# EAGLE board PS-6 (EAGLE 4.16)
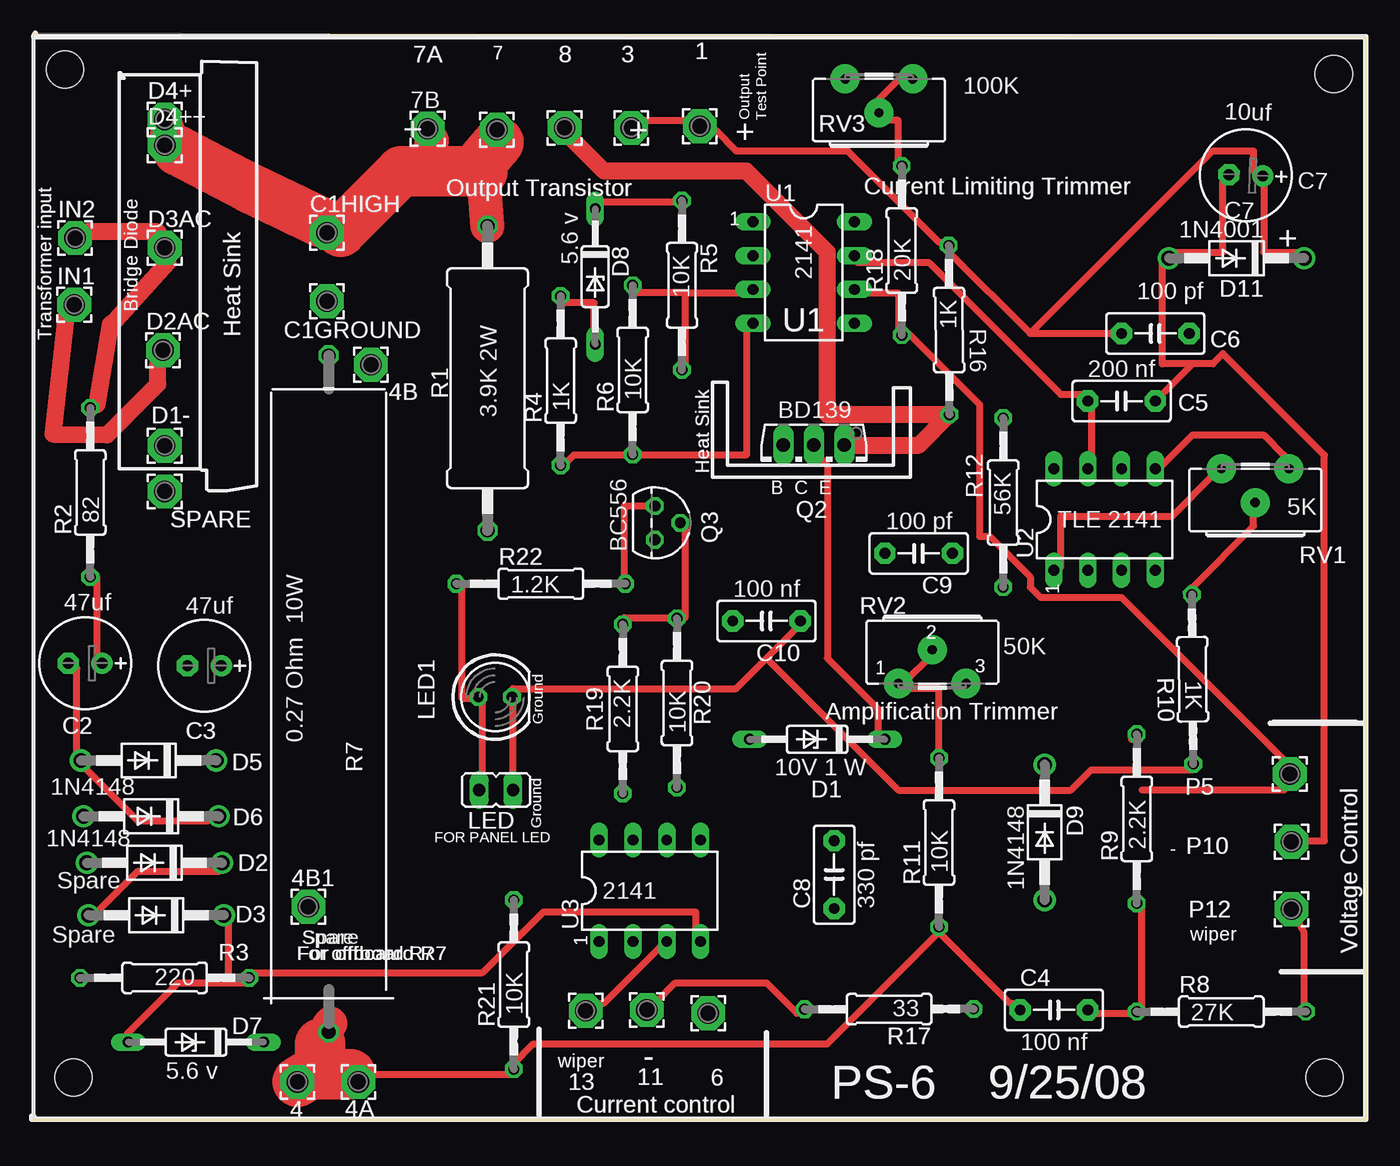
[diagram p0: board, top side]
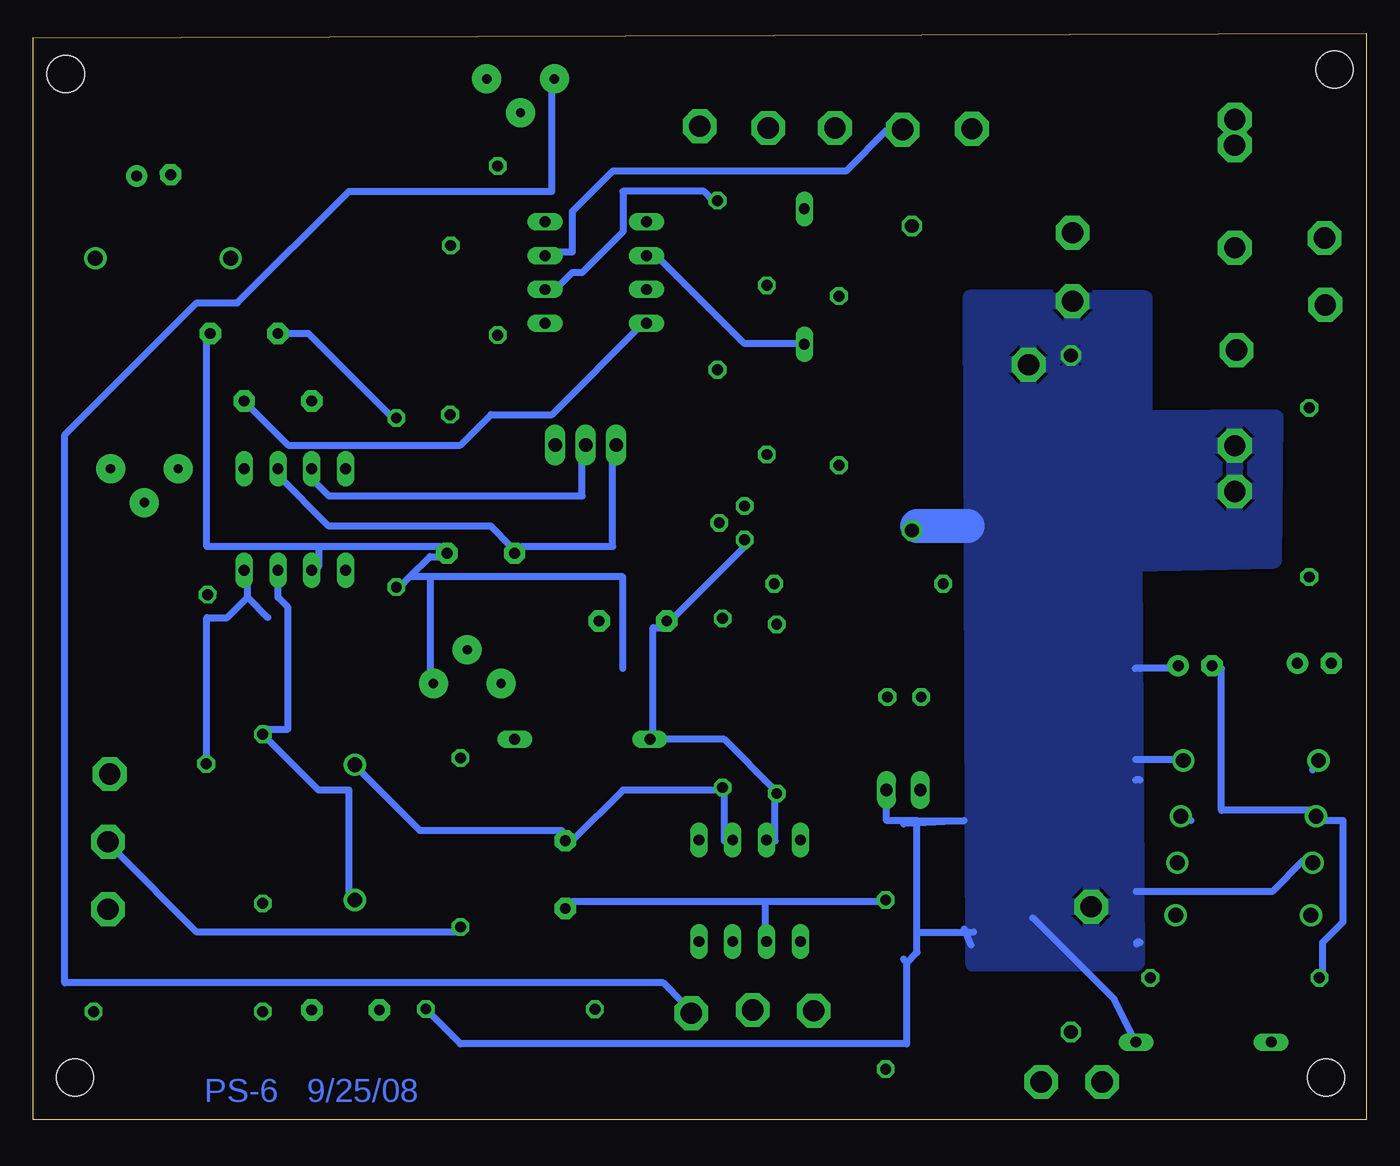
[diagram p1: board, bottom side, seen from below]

Size 100.13 x 81.59 mm. Coordinates in mm from the lower left corner, seen from the top.
Outline: 0,0 100.13,0 100.13,81.27 0,81.59 0,0
Copper layers (1*16): Top 0.035mm / dielectric 1.5mm / Bottom 0.035mm
Design rules "default": minimum track width 15mil, minimum drill 6mil, track to track 10mil, track to pad 8mil, pad to pad 8mil, via to via 8mil, smd to smd 8mil, copper to edge 20mil, drill to drill 6mil, minimum pad ring 10mil, minimum via ring 15mil, stop-mask expansion 4mil, vias tented up to drill 0mil, thermal gap 10mil
Net classes: 0 default: width 0.508 mm, drill 0.635 mm; 1 POWER: width 0.508 mm, drill 0.635 mm; 2 HI power: width 0.508 mm, drill 0.508 mm; 3 VPower: width 0.508 mm, drill 0.508 mm
Holes 2.8 mm at 97.69,78.54 96.99,3.17 3.01,3.17 2.38,78.86

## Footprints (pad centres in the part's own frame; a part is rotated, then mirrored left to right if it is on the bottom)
2,54/0,8 = drill 1.6 pad 2.54 octagon: 1 0,0
E2,5-7 = drill 0.813 pad 1.6 round: + -1.27,0 | drill 0.813 pad 1.6 octagon: - 1.27,0
C5B3 = drill 0.813 pad 1.6 octagon: 1 -2.54,0; 2 2.54,0
DO35Z10 = drill 0.813 long: A 5.08,0; C -5.08,0
DO41-10 = drill 1.118 round: A 5.08,0; C -5.08,0
JP1 = drill 0.914 long: 1 0,-1.27; 2 0,1.27
LED5MM = drill 0.813 octagon: A -1.27,0; K 1.27,0
TO126AV = drill 1.016 long: B 2.286,-1.27; C 0,-1.27; E -2.286,-1.27
TO92 = drill 0.813 octagon: 1 1.27,0; 2 0,1.905; 3 -1.27,0
0617/22 = drill 1.016 octagon: 1 -11.43,0; 2 11.43,0
0207/12 = drill 0.813 octagon: 1 -6.35,0; 2 6.35,0
POWERRESISTOR = drill 1.016 octagon: 1 -12.7,0; 2 38.1,0
POTT = drill 0.7 pad 2.184 round: P$1 -2.54,0; P$2 2.54,0; P$3 0,2.54
DIL08 = drill 0.813 long: 1 -3.81,-3.81; 2 -1.27,-3.81; 3 1.27,-3.81; 4 3.81,-3.81; 5 3.81,3.81; 6 1.27,3.81; 7 -1.27,3.81; 8 -3.81,3.81

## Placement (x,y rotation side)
1  [2,54/0,8]  50.06,74.61 0 top
3  [2,54/0,8]  44.92,74.48 90 top
4  [2,54/0,8]  19.85,2.84 0 top
4A  [2,54/0,8]  24.42,2.84 0 top
4B  [2,54/0,8]  25.36,56.7 0 top
4B1  [2,54/0,8]  20.66,16 0 top
6  [2,54/0,8]  50.7,8 0 top
7A  [2,54/0,8]  34.82,74.35 0 top
7B  7  [2,54/0,8]  29.62,74.42 0 top
8  [2,54/0,8]  39.9,74.48 0 top
11  11  [2,54/0,8]  46.09,8.25 0 top
13  [2,54/0,8]  41.5,8.19 0 top
C1GROUND  [2,54/0,8]  22.06,61.46 0 top
C1HIGH  [2,54/0,8]  22.06,66.61 0 top
C2  47uf  [E2,5-7]  3.9,34.28 180 top
C3  47uf  [E2,5-7]  12.85,34.09 180 top
C4  100 nf  [C5B3]  76.67,8.25 0 top
C5  200 nf  [C5B3]  81.75,53.97 180 top
C6  100 pf  [C5B3]  84.29,59.05 180 top
C7  10uf  [E2,5-7]  91.08,70.92 177.9 top
C8  330 pf  [C5B3]  60.16,18.41 90 top
C9  100 pf  [C5B3]  66.51,42.54 180 top
C10  100 nf  [C5B3]  55.08,37.46 180 top
D1  10V 1 W  [DO35Z10]  58.89,28.57 180 top
D1-  [2,54/0,8]  9.87,50.62 0 top
D2  Spare  [DO41-10]  9.11,19.3 180 top
D2AC  [2,54/0,8]  9.74,57.8 0 top
D3  Spare  [DO41-10]  9.23,15.36 180 top
D3AC  [2,54/0,8]  9.87,65.48 0 top
D4+  [2,54/0,8]  9.87,75.12 0 top
D4++  [2,54/0,8]  9.88,73.18 0 top
D5  1N4148  [DO41-10]  8.66,26.98 180 top
D6  1N4148  [DO41-10]  8.85,22.79 180 top
D7  5.6 v  [DO35Z10]  12.22,5.84 180 top
D8  5.6 v  [DO35Z10]  42.21,63.32 270 top
D9  1N4148  [DO41-10]  75.97,21.58 270 top
D11  1N4001  [DO41-10]  90.39,64.7 180 top
IN1  [2,54/0,8]  3.07,61.19 0 top
IN2  [2,54/0,8]  3.14,66.21 0 top
LED  [JP1]  34.76,24.76 90 top
LED1  [LED5MM]  34.7,31.74 0 top
P5  [2,54/0,8]  94.39,25.97 0 top
P10  [2,54/0,8]  94.51,20.89 0 top
P12  [2,54/0,8]  94.51,15.81 0 top
Q2  BD139  [TO126AV]  58.64,49.4 180 top
Q3  BC556  [TO92]  46.7,44.83 270 top
R1  3.9K 2W  [0617/22]  34.12,55.68 90 top
R2  82  [0207/12]  4.28,47.11 90 top
R3  220  [0207/12]  9.87,10.66 180 top
R4  1K  [0207/12]  39.61,55.5 90 top
R5  10K  [0207/12]  48.73,62.67 270 top
R6  10K  [0207/12]  45.02,56.31 90 top
R7  0.27 Ohm 10W  [POWERRESISTOR]  22.19,44.7 270 top
R8  27K  [0207/12]  89.24,8.12 0 top
R9  2.2K  [0207/12]  82.89,22.6 90 top
R10  1K  [0207/12]  87.08,33.08 90.5 top
R11  10K  [0207/12]  68.03,20.82 90 top
R12  56K  [0207/12]  72.86,46.35 270 top
R16  1K  [0207/12]  68.8,59.3 270.2 top
R17  33  [0207/12]  64.29,8.31 180.1 top
R18  20K  [0207/12]  65.24,65.27 90 top
R19  2.2K  [0207/12]  44.29,30.86 270 top
R20  10K  [0207/12]  48.35,31.3 90 top
R21  10K  [0207/12]  36.09,10.16 90 top
R22  1.2K  [0207/12]  38.13,40.25 0 top
RV1  5K  [POTT]  91.78,48.89 180 top
RV2  50K  [POTT]  67.53,32.76 0 top
RV3  100K  [POTT]  63.53,78.16 180 top
SPARE  [2,54/0,8]  9.88,47.19 0 top
U1  2141  [DIL08]  57.87,63.62 270 top
U2  TLE 2141  [DIL08]  80.48,45.08 0 top
U3  2141  [DIL08]  46.32,17.2 0 top

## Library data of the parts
1 3 4 4A 4B 4B1 6 7A 7B 8 11 13 C1GROUND C1HIGH D1- D2AC D3AC D4+ D4++ IN1 IN2 P5 P10 P12 SPARE = wirepad
C2 C3 C7 R1-R6 R8-R12 R16-R22 = rcl
C4-C6 C8-C10 = capacitor-wima
D1-D3 D5-D9 D11 = diode
LED = jumper
LED1 = led
Q2 = transistor-power
Q3 = transistor-pnp
R7 RV1-RV3 = pott
U1-U3 = linear

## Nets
AMP11: 11.1 R17.2
N$1: C8.2 D9.C R20.1 U3.6
N$2: 4B1.1 4B.1 C1GROUND.1 C3.+ C10.1 D1-.1 D2.A D5.C D7.C LED1.K LED.1 R1.1 R7.1 R10.1 R17.1 SPARE.1 U2.4
N$3: 4.1 4A.1 C4.1 C5.1 C7.- D11.A P10.1 R4.1 R6.1 R7.2 R11.1 R21.1 U1.4
N$4: R18.2 RV3.P$1 RV3.P$3
N$5: R11.2 RV2.P$1 RV2.P$3
N$6: 13.1 U3.3
N$7: D8.C P5.1 R5.1 R18.1 U1.6
N$8: D3.C D7.A R3.1 U3.4
N$9: Q3.3 R22.2
N$10: LED1.A LED.2 R22.1
N$11: C9.2 Q2.B U2.6
N$12: P12.1 R8.2
N$13: Q3.2 R19.1 R20.2
N$14: 6.1 RV3.P$2
N$15: C8.1 R21.2 U3.2
N$16: 1.1 3.1 C6.2 C7.+ D11.C R12.1 R16.1
N$17: D2.C D3.A
N$18: RV1.P$1 U2.5
N$19: 8.1 Q2.E R16.2
N$20: C2.+ R2.1
N$21: R5.2 R6.2 U1.3
N$22: D8.A R4.2 U1.2
N$23: D9.A R9.2 U2.3
N$24: C4.2 R8.1 R9.1
N$25: D2AC.1 IN1.1
N$26: RV1.P$2 U2.1
N$27: C2.- D5.A D6.C
N$28: R10.2 RV1.P$3
N$29: 7A.1 7B.1 C1HIGH.1 C5.2 D1.C D4++.1 D4+.1 Q2.C R1.2 U1.7 U2.7
N$31: C6.1 C9.1 R12.2 RV2.P$2 U2.2
N$32: C3.- D6.A R3.2
N$33: C10.2 D1.A Q3.1 R19.2 U3.7
N$37: D3AC.1 IN2.1 R2.2

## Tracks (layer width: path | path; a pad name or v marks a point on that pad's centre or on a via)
AMP11
  Top 0.508: R17.2 57.37,8 55.08,10.28 48.22,10.28 46.7,8.76 11.1
N$1
  Top 0.508: D9.C 75.65,26.28
  Bottom 0.508: U3.6 48.22,20.95 48.22,24.76 R20.1 48.98,24.76 55.84,24.76 59.65,20.95 C8.2 60.41,21.71 71.08,21.71 75.65,26.28 D9.C
N$2
  Top 0.508: 55.08,34.67 52.79,32.38 36.03,32.38 LED1.K 36.03,31.62 LED.1 | 55.08,34.67 57.37,36.95 C10.1 | R7.1 22.31,56.76 | 55.08,34.67 64.99,24.76 77.94,24.76 79.46,26.28 87.08,26.28 R10.1
  Bottom 0.508: R17.1 70.32,8 68.03,5.71 34.51,5.71 34.51,11.81 | 34.51,11.81 34.76,12.06 | LED.1 36.03,22.47 33.74,22.47 | 33.74,22.47 30.19,22.47 33.73,22.28 | 33.73,22.28 34.76,22.22 | 34.51,11.81 33.74,12.57 33.74,14.09 | 30.06,14.04 29.68,13.14 | 30.06,14.04 30.19,14.35 | 33.74,14.09 33.74,22.47 | 33.74,22.47 33.73,22.28 | 17.24,13.33 16.98,13.33 17.24,13.19 | C3.+ 14.69,33.9 16.98,33.9 17.37,33.9 | 16.98,25.52 17.32,25.52 | 29.93,14.09 30.06,14.04 | 33.74,14.09 29.93,14.09 | 29.93,14.09 29.5,14.1 | 33.74,44.57 R1.1 | 29.61,44.56 29.93,44.57 | D5.C 13.93,27.05 16.98,27.05 17.33,27.04 | D2.A 4.79,19.43 7.07,17.14 16.98,17.14 17.27,17.14 | 25.04,15.17 18.95,9.08 D7.C | 84.04,39.24 85.56,37.71 87.08,37.71 87.08,27.05 R10.1 | 84.04,39.24 84.04,40.76 U2.4 | 84.04,39.24 82.51,37.71 | C10.1 58.13,37.71
  Bottom 2.54: 29.93,44.57 33.74,44.57
  pour Bottom: 6.82,52.7 16.66,52.64 16.66,61.65 29.68,61.72 29.49,11.74 17.23,11.81 17.42,41.78 6.95,42.03
N$3
  Top 0.508: 87.08,56.76 88.61,56.76 89.37,57.53 96.99,49.91 96.99,20.95 95.47,20.95 P10.1 | 87.08,56.76 C5.1 | 20.79,3.42 21.55,3.42 | 23.84,3.42 4A.1 25.36,3.42 36.03,3.42 R21.1 36.03,4.19 37.55,5.71 59.65,5.71 68.03,14.09 | 68.03,14.09 73.37,8.76 74.13,8.76 C4.1 | 68.03,14.09 R11.1 | R4.1 39.84,49.14 40.6,49.91 44.41,49.91 R6.1 45.17,49.91 53.56,49.91 53.56,59.81 U1.4 | 22.31,7.23 R7.2 | 87.08,56.76 84.8,56.76 84.8,64.38 D11.A 85.56,65.15 89.37,65.15 89.37,70.48 C7.-
  Top 2.54: 21.55,5.71 22.31,7.23
  Top 3.81: 21.55,5.71 21.55,3.42 23.84,3.42 | 4.1 20.79,3.42
  Bottom 0.508: 53.56,59.81 U1.4 54.32,59.81 61.18,52.95 65.75,52.95 68.03,50.67 80.99,50.67 C5.1 | P10.1 93.94,20.19 87.85,14.09 68.03,14.09 R11.1 | D11.A 85.56,65.15
N$4
  Top 0.508: R18.2 64.99,72 64.99,75.05 64.22,75.05 RV3.P$3 63.46,76.58 64.99,78.1 RV3.P$1
N$5
  Top 0.508: R11.2 68.03,32.38 65.75,32.38 RV2.P$1 65.75,33.14 67.27,34.67 RV2.P$3
N$6
  Top 0.508: U3.3 47.46,13.33 42.89,8.76 42.13,8.76 13.1
N$7
  Top 0.508: D8.C 42.13,68.96 48.22,68.96 R5.1 | U1.6 61.94,62.1 64.99,62.1 64.99,59.05 R18.1 65.75,59.05 71.08,53.72 71.08,43.81 71.84,43.81 74.89,40.76 74.89,40 75.65,39.24 81.75,39.24 93.94,27.05 P5.1 93.94,24.76 83.27,24.76
  Bottom 0.508: U1.6 61.18,62.1 59.65,63.62 58.89,63.62 55.84,66.67 55.84,69.72 49.75,69.72 48.98,68.96 R5.1
N$8
  Top 0.508: 14.69,10.28 16.22,10.28 R3.1 16.22,11.04 33.74,11.04 38.32,15.62 49.75,15.62 49.75,13.33 U3.4 | 14.69,10.28 10.88,10.28 7.07,6.47 D7.A | 14.69,10.28 14.69,14.85 D3.C
N$9
  Top 0.508: Q3.3 44.41,46.1 44.41,40.76 R22.2
N$10
  Top 0.508: LED.2 33.74,24.76 33.74,31.62 LED1.A 32.98,31.62 32.22,31.62 32.22,40 R22.1
N$11
  Bottom 0.508: U2.6 81.75,48.38 77.94,44.57 65.75,44.57 64.22,43.05 C9.2 63.46,43.05 56.6,43.05 56.6,50.67 Q2.B
N$12
  Top 0.508: R8.2 95.47,8.76 95.47,14.09 P12.1
N$13
  Top 0.508: R19.1 44.41,37.71 48.22,37.71 R20.2 48.98,37.71 48.98,44.57 Q3.2
N$14
  Bottom 0.508: RV3.P$2 61.18,77.34 61.18,69.72 76.42,69.72 84.8,61.34 87.85,61.34 97.75,51.43 97.75,10.28 52.79,10.28 51.27,8.76 6.1
N$15
  Bottom 0.508: 45.17,16.38 59.65,16.38 C8.1 | 45.17,16.38 36.03,16.38 R21.2 | 45.17,16.38 45.17,13.33 U3.2
N$16
  Top 0.508: 74.89,59.05 68.8,65.15 R16.1 68.8,65.91 68.03,65.91 61.18,72.77 52.79,72.77 51.27,74.29 1.1 48.98,75.05 45.94,75.05 3.1 | 74.89,59.05 C6.2 | D11.C 95.47,65.15 92.42,65.15 92.42,70.48 C7.+ 91.66,71.24 91.66,72.77 88.61,72.77 74.89,59.05
  Bottom 0.508: R12.1 73.37,52.95 79.46,59.05 C6.2
N$17
  Top 0.508: D3.A 4.79,15.62 7.84,18.66 13.93,18.66 D2.C
N$18
  Top 0.508: U2.5 84.8,49.14 87.08,51.43 92.42,51.43 93.94,49.91 RV1.P$1
N$19
  Top 0.508: 68.8,52.95 R16.2
  Top 1.27: Q2.E 66.51,50.67 68.8,52.95 59.65,52.95 59.65,65.15 53.56,71.24 42.89,71.24 40.6,73.53 8.1
N$20
  Top 0.508: R2.1 4.79,40.76 4.79,34.67 C2.+
N$21
  Top 0.508: 48.98,62.1 48.98,56.76 R5.2 | 48.98,62.1 45.17,62.1 R6.2 | 48.98,62.1 53.56,62.1 U1.3
N$22
  Top 0.508: D8.A 42.13,58.29 42.13,61.34 39.84,61.34 R4.2
  Bottom 0.508: U1.2 53.56,65.15 46.7,58.29 42.13,58.29 D8.A
N$23
  Top 0.508: R9.2 82.51,28.57
  Bottom 0.508: D9.A 76.42,17.14 76.42,24.76 78.7,24.76 R9.2 82.51,29.33 80.99,29.33 80.99,38.48 81.75,39.24 U2.3
N$24
  Top 0.508: C4.2 79.46,8 82.51,8 R8.1 83.27,8 83.27,16.38 R9.1
N$25
  Top 0.508: 2.5,60.57 IN1.1
  Top 1.27: 2.5,60.57 1.49,51.49 5.55,51.43 9.36,55.24 9.36,56.76 D2AC.1
N$26
  Top 0.508: U2.1 77.18,41.52 77.18,45.33 85.56,45.33 88.61,48.38 RV1.P$2
N$27
  Top 0.508: 2.5,33.9 C2.- 3.26,33.9 3.26,27.81 D5.A 4.03,26.28 7.84,22.47 13.17,22.47 D6.C
  Bottom 0.508: D6.C 13.17,22.47 | D5.A 4.03,26.28
N$28
  Top 0.508: R10.2 87.08,40 91.66,44.57 91.66,45.33 RV1.P$3
N$29
  Top 0.508: 34.95,73.4 7A.1 | 23.08,66.67 C1HIGH.1 21.55,67.43 | 33.74,71.24 R1.2 | 10.88,72.77 D4++.1 | U1.7 61.94,64.38 67.27,64.38 77.18,54.48 78.7,54.48 C5.2 79.46,53.72 79.46,49.14 U2.7 | D1.C 63.46,28.57 63.46,30.86 59.65,34.67 59.65,49.14 58.13,50.67 Q2.C
  Top 1.27: 29.93,73.53 7B.1
  Top 2.54: D4++.1 10.12,74.29 D4+.1 | R1.2 33.74,72 | 29.93,71.24 29.93,73.53
  Top 3.81: 33.74,72 34.95,73.4 | 23.08,66.67 27.65,71.24 29.93,71.24 33.74,71.24 | 10.88,72.77 16.22,69.97 21.55,67.43
  Bottom 0.508: Q2.C 58.89,50.67 58.89,46.86 77.94,46.86 79.46,48.38 U2.7 | R1.2 34.51,67.43 | 7A.1 36.03,74.29 39.08,71.24 56.6,71.24 59.65,68.19 59.65,65.15 61.18,65.15 U1.7
N$31
  Bottom 0.508: 71.84,40.76 70.32,42.29 69.56,42.29 C9.1 69.56,43.05 78.7,43.05 | 71.84,40.76 72.61,40 R12.2 | 78.7,43.05 78.7,41.52 U2.2 | 78.7,43.05 87.08,43.05 87.08,58.29 C6.1 | 55.84,33.9 55.84,40.76 70.32,40.76 | 70.32,40.76 71.84,40.76 | 70.32,32.38 RV2.P$2 70.32,33.14 70.32,40.76
N$32
  Bottom 0.508: R3.2 3.26,11.04 3.26,13.33 1.74,14.85 1.74,22.47 3.26,22.47 D6.A 4.03,23.24 10.88,23.24 10.88,33.9 C3.-
N$33
  Bottom 0.508: Q3.1 46.7,43.05 52.03,37.71 C10.2 52.79,36.95 53.56,36.95 53.56,28.57 | U3.7 44.41,20.95 44.41,24 R19.2 44.41,24.76 48.22,28.57 53.56,28.57 | 53.56,28.57 D1.A
N$37
  Top 0.508: 5.8,59.75 5.8,59.62 | R2.2 4.79,53.72
  Top 1.27: 4.79,53.72 5.8,59.75 | 5.8,59.62 10.12,64.38 D3AC.1 9.36,66.67 4.03,66.67 IN2.1

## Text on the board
Bottom: PS-6 9/25/08
tOrigins: R7A | U2 | U2 | U3 | Output | Ground
tNames: 7 | Output | Test Point | + | + | + | Output Transistor | Current Limiting Trimmer | 1 | + | Bridge Diode | Transformer input | Heat Sink | U1 | Heat Sink | B C E | 1 | 2 | 1 | 3 | Amplification Trimmer | Ground | Ground | FOR PANEL LED | - | wiper | Spare | 1 | Voltage Control | For offboard R7 | For offboard R7 | For offboard R7 | wiper | - | PS-6 9/25/08 | Current control
_tsilk: 3 | 7 | 1 | 7A | 8 | 100K | D4+ | RV3 | 10uf | D4++ | 7 | Output | Test Point | + | + | + | Output Transistor | Current Limiting Trimmer | C7 | U1 | IN2 | C1HIGH | 5.6 v | 1N4001 | D3AC | 1 | 2141 | D8 | R5 | 10K | + | IN1 | 20K | 100 pf | D11 | R18 | 1K | Bridge Diode | Transformer input | D2AC | Heat Sink | C1GROUND | U1 | C6 | 200 nf | Heat Sink | C5 | 4B | R1 | 10K | BD139 | 3.9K 2W | 1K | R6 | D1- | R4 | R12 | 56K | BC556 | B C E | Q2 | Q3 | 100 pf | 82 | SPARE | TLE 2141 | 5K | R2 | R22 | U2 | RV1 | 0.27 Ohm 10W | 100 nf | C9 | 47uf | 1.2K | 1 | 47uf | RV2 | 2 | C10 | 1 | 3 | 50K | R19 | 2.2K | Amplification Trimmer | 1K | C2 | C3 | LED1 | Ground | R20 | R10 | R7 | 10K | D5 | 10V 1 W | 1N4148 | D1 | 1N4148 | D9 | P5 | D6 | LED | 1N4148 | Ground | FOR PANEL LED | D2 | R9 | 2.2K | - | P10 | Spare | 10K | 4B1 | R11 | 2141 | D3 | C8 | 330 pf | Spare | P12 | wiper | U3 | R3 | Spare | 1 | Voltage Control | For offboard R7 | For offboard R7 | For offboard R7 | 220 | C4 | R8 | 11 | 33 | D7 | 10K | 27K | R21 | R17 | wiper | 100 nf | 5.6 v | - | 11 | 6 | 4 | 4A | 13 | PS-6 9/25/08 | Current control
